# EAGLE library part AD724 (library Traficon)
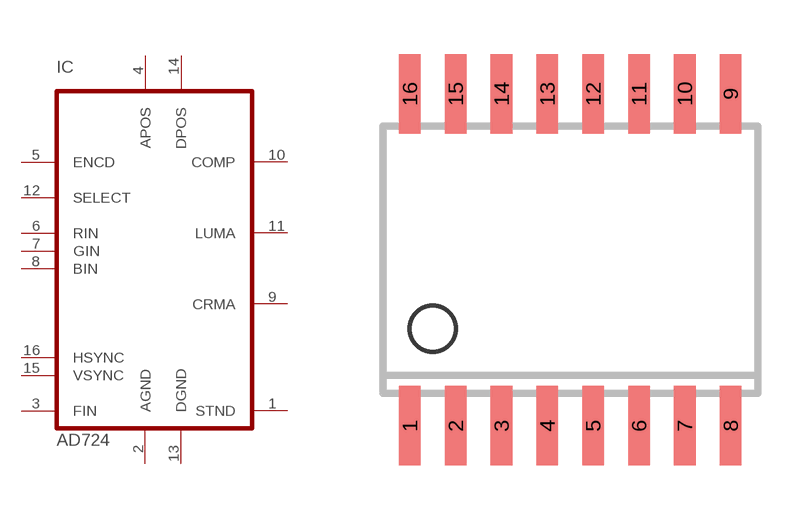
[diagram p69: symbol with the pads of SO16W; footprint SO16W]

Designator prefix IC

## AD724JRZ  [SO16W]
1  STND
2  AGND
3  FIN
4  APOS
5  ENCD
6  RIN
7  GIN
8  BIN
9  CRMA
10  COMP
11  LUMA
12  SELECT
13  DGND
14  DPOS
15  VSYNC
16  HSYNC

## Footprint SO16W (pad centres in mm)
SMALL OUTLINE INTEGRATED CIRCUIT wide body 7.5 mm/JEDEC MS-013AA
smd 0.6 x 2.2: 1 -4.445,-4.6; 2 -3.175,-4.6; 3 -1.905,-4.6; 4 -0.635,-4.6; 5 0.635,-4.6; 6 1.905,-4.6; 7 3.175,-4.6; 8 4.445,-4.6; 9 4.445,4.6; 10 3.175,4.6; 11 1.905,4.6; 12 0.635,4.6; 13 -0.635,4.6; 14 -1.905,4.6; 15 -3.175,4.6; 16 -4.445,4.6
